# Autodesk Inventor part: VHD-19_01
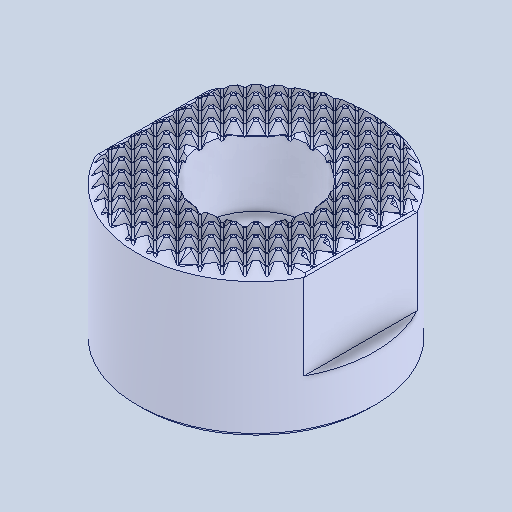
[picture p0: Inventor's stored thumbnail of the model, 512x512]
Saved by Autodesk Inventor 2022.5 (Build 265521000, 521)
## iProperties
Created: 2024-05
Part Number: VHD-19_01
Material: 一般
Document SubType Name: Modeling
Designer: ImaoCorp
Density: 1 g/cm^3
Appearance: 既定
Author: ImaoCorp
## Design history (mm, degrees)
feature "VHD-19_01"
node "ソリッド1"
